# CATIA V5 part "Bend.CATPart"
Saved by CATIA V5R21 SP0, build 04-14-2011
Part number: Bend
Bounding box of the stored display mesh (mm): x -50 to 50, y -150 to 15, z -50 to 115
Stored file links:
  D:\CATIA V5R21 E-RESOURCES\CATIA-V5R21\catia-v5r21-Prts\c12_catia_v5r21_prt\c12_catia_v5r21figr_12-39\Bend.CATPart
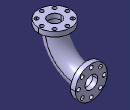
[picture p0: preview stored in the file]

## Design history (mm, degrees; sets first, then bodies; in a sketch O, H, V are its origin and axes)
Body1 (main body)
  Sketch1 on yz-plane, origin (0, 0, 0), H (0, 1, 0), V (0, 0, 1)
    arc A1 centre (0, 100) radius 100 from (-100, 100) to (0, 0) ccw
    point P1 (0, 100)
    coincidence: P1 V
  Sketch2 on zx-plane, origin (0, 0, 0), H (-1, 0, 0), V (0, 0, 1)
    circle A1 centre (0, 0) radius 30
    point P1 (0, -30)
    radius A1 = 30
    coincidence: A1 P1, P1 V
  Rib1: profile Sketch2, centre curve Sketch1
  Sketch3 on face of Rib1, origin (0, 0, 0), H (-1, 0, 0), V (0, 0, 1)
    circle A1 centre (0, 0) radius 50
    point P1 (0, -50)
    radius A1 = 50
    coincidence: A1 P1, P1 V
  Pad1: profile Sketch3, direction (0, 1, 0), length 15
  Sketch4 on face of Rib1, origin (0, 0, 100), H (1, 0, 0), V (0, 1, 0)
    circle A1 centre (0, -100) radius 50
    point P1 (0, -100)
    reference projected circle E1 centre (0, -100) radius 30 from edge [face of Rib1 | face of Rib1]
    radius A1 = 50
    coincidence: P1 V
    concentricity: A1 E1
  Pad2: profile Sketch4, direction (0, 0, 1), length 15
  Sketch5 on face of Pad1, origin (0, 15, 0), H (-1, 0, 0), V (0, 0, 1)
    circle A1 centre (0, 0) radius 20
    radius A1 = 20
  Sketch6 on yz-plane, origin (0, 0, 0), H (0, 1, 0), V (0, 0, 1)
    projected arc E1 centre (0, 100) radius 100 from (-100, 100) to (0, 0) ccw from edge of Sketch1
    line L1 (-100, 100) -> (-100, 115)
    point P3 (-100, 115)
    line L2 (0, 0) -> (15, 0)
    point P4 (15, 0)
    reference projected line E2 (15, 50) -> (15, -50) from edge [face of Pad1 | face of Pad1]
    reference projected line E3 (-50, 115) -> (-150, 115) from edge [face of Pad2 | face of Pad2]
    tangency: L1 E1, L2 E1
    coincidence: P4 E2, P3 E3
  Slot1: profile Sketch5, centre curve Sketch6
  Sketch7 on face of Pad1, origin (0, 15, 0), H (-1, 0, 0), V (0, 0, 1)
    circle A1 centre (0, -40) radius 6
    point P1 (0, -40)
    radius A1 = 6
    distance H P1 = 40
    coincidence: P1 V
  Pocket1: profile Sketch7, direction (0, -1, 0), length 15
  CircPattern1: of Pocket1, instances 8, angular step 45, axis from face of Pad1
  Sketch8 on face of Pad2, origin (0, 0, 115), H (1, 0, 0), V (0, 1, 0)
    circle A1 centre (0, -140) radius 6
    point P1 (0, -140)
    reference projected point E1 (0, -100) from vertex of Sketch1
    radius A1 = 6
    distance E1 P1 = 40
    coincidence: P1 V
  Pocket2: profile Sketch8, direction (0, 0, -1), length 15
  CircPattern2: of Pocket2, instances 8, angular step 45, axis from face of Pad2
